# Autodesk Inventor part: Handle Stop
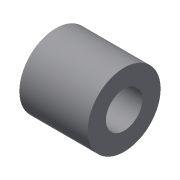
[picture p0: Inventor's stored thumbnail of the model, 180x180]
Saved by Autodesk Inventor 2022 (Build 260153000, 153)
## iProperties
Created: 2002-02
Part Number: Handle Stop
Document SubType Name: Modeling
Designer: ***
Density: 1 g/cm^3
Material: Generic
Appearance: Default
Control State: 0
Master: False
Checked Out: False
Shininess: 77.0
Length Units: 11269
Angle Units: 11279
Time Units: 11290
Mass Units: 11283
Length Display Precision: 3
Angle Display Precision: 2
Compacted: True
Density: 0.0
Volumn: 0.0
Area: 0.0
PropertySet Name: Model Information
Author: ***
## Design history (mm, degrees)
sketch "Sketch1"
  geometry: L1 (0, 0)-(0, -2); L2 (0, -2)-(8, -2); L3 (8, -2)-(8, 13); L4 (8, 13)-(4, 13); L5 (4, 13)-(4, 0); L6 (4, 0)-(0, 0)
  constraints: 12 end point, 4 parallel, 1 perpendicular, 1 vertical
  dimensions: "d0" = 16 diameter of L3 L1; "d1" = 8 diameter of L5 L1; "d2" = 2 distance of L1.start L1.end; "d3" = 15 distance of L2.end L3.end
revolve "Revolution1" sketch "Sketch1" stored, may be unused: angle "d4" = 90 deg
body "Solid1"
